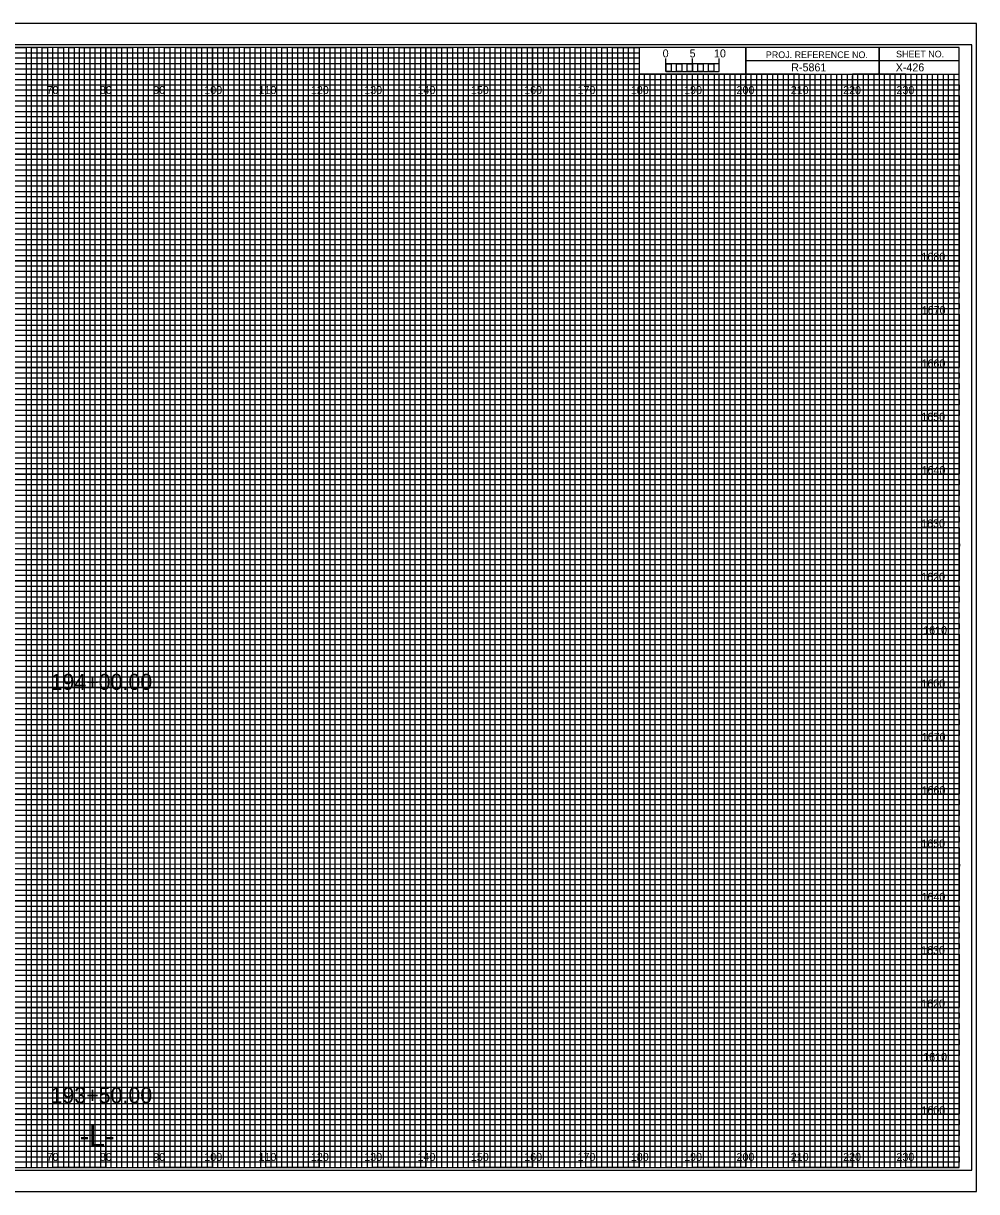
# Model space of a CAD drawing. Extents: x -13 to 323, y -5 to 6154.
# Drawn here: x 144.5 to 323.3, y 4835.5 to 5054.5 of the extents above; entities that cross this region are included whole.
import ezdxf

# ---------------------------------------------------------------- set-up
doc = ezdxf.new("R2010")
doc.units = 0
for name, color, linetype in [('Exist CMT Ground Line', 7, 'Continuous'), ('Prop Horizontal Alignment', 7, 'Continuous'), ('Prop Retaining Wall', 7, 'Continuous'), ('Prop XS Alignment Label', 7, 'Continuous'), ('Prop XS Bar Scale Labels', 7, 'Continuous'), ('Prop XS DDE', 7, 'Continuous'), ('Prop XS DDE Elevations', 7, 'Continuous'), ('Prop XS DDE Slope Text', 7, 'Continuous'), ('Prop XS Earthwork Shape', 7, 'Continuous'), ('Prop XS Elevation Labels', 7, 'Continuous'), ('Prop XS Project Number', 7, 'Continuous'), ('Prop XS Sheet Number', 7, 'Continuous'), ('Prop XS Station Labels', 7, 'Continuous'), ('Raster_Level_0', 7, 'Continuous'), ('Scratch_Level_3', 7, 'Continuous'), ('Sheet Cutting Line CELL', 7, 'Continuous')]:
    doc.layers.add(name, color=color, linetype=linetype)

msp = doc.modelspace()

# ---------------------------------------------------------------- linework, layer by layer
at = {"layer": 'Exist CMT Ground Line'}
for p, q in [((265, 5045.49), (265, 5047.9)), ((265, 5046.9), (265, 5047.9)), ((270, 5045.49), (270, 5047.9)), ((275, 5045.49), (275, 5047.9)), ((275, 5046.9), (275, 5047.9))]:
    msp.add_line(p, q, dxfattribs=at)
for points in [[(275, 5046.9), (265, 5046.9), (265, 5045.49), (275, 5045.49)], [(265, 5046.9), (266, 5046.9), (266, 5045.49), (265, 5045.49)], [(267, 5046.9), (268, 5046.9), (268, 5045.49), (267, 5045.49)], [(269, 5046.9), (270, 5046.9), (270, 5045.49), (269, 5045.49)], [(271, 5046.9), (272, 5046.9), (272, 5045.49), (271, 5045.49)], [(273, 5046.9), (274, 5046.9), (274, 5045.49), (273, 5045.49)]]:
    msp.add_lwpolyline(points, close=True, dxfattribs=at)
at = {"layer": 'Prop Retaining Wall'}
for p, q in [((0, 5049), (260, 5049)), ((260, 5047.98), (0, 5047.98)), ((260, 5049), (260, 5047.98)), ((0, 5047), (260, 5047)), ((260, 5045.89), (0, 5045.89)), ((260, 5047), (260, 5045.89)), ((0, 5044), (320, 5044))]:
    msp.add_line(p, q, dxfattribs=at)
for points in [[(0, 5043), (270, 5043), (320, 5043), (320, 5042), (0, 5042)], [(0, 5041), (320, 5041), (320, 5039), (0, 5039)], [(0, 5038), (320, 5038), (320, 5037), (0, 5036.98)], [(0, 5036), (320, 5036), (320, 5034), (0, 5034)], [(0, 5033), (320, 5033), (320, 5032), (0, 5032)], [(0, 5031), (320, 5031), (320, 5029), (0, 5029)], [(0, 5028), (320, 5028), (320, 5027), (0, 5027)], [(0, 5026), (320, 5026), (320, 5024), (0, 5024)], [(0, 5023), (320, 5023), (320, 5022), (0, 5022)], [(0, 5021), (320, 5021), (320, 5019), (0, 5019)], [(0, 5018), (320, 5018), (320, 5017), (0, 5017)], [(0, 5016), (320, 5016), (320, 5013.95), (320, 5013), (320, 5012), (0, 5012)], [(0, 5014), (320, 5014), (320, 5013), (0, 5013)], [(0, 5011), (320, 5011), (320, 5009), (0, 5009.03)], [(0, 5009.03), (320, 5009), (320, 5008), (0, 5008)], [(0, 5007), (320, 5007), (320, 5006), (0, 5006)], [(0, 5004), (320, 5004), (320, 5003), (0, 5003)], [(0, 5002), (320, 5002), (320, 5001), (0, 5001)], [(-0.07, 4998.89), (320, 4998.89), (320, 4997.88), (-0.07, 4997.88)], [(0, 4997), (320, 4997), (320, 4996), (0, 4996)], [(0, 4994), (320, 4994), (320, 4993), (0, 4993)], [(0, 4992), (320, 4992), (320, 4991), (0, 4991)], [(0, 4989), (320, 4989), (320, 4988), (0, 4988)], [(0, 4987), (320, 4987), (320, 4986), (0, 4986)], [(0, 4984), (320, 4984), (320, 4983), (0, 4983)], [(0, 4982), (320, 4982), (320, 4981), (0, 4981)], [(0, 4979), (320, 4979), (319.99, 4977.98), (0, 4978)], [(0, 4977), (320, 4977), (320, 4976), (0, 4976)], [(0, 4974), (320, 4974), (320, 4973), (0, 4973)], [(0, 4972), (320, 4972), (320, 4971), (0, 4971)], [(0, 4969), (320, 4969), (320, 4968), (0, 4968)], [(0, 4967), (320, 4967), (320, 4966), (0, 4966)], [(0, 4964), (320, 4964), (320, 4963), (0, 4963)], [(0, 4962), (320, 4962), (320, 4961), (0, 4961)], [(0, 4959), (320, 4959), (320, 4958), (0, 4958)], [(0, 4956.99), (320.07, 4956.91), (320, 4956), (0, 4956)], [(0, 4954), (320, 4954), (320, 4953), (0, 4953)], [(0, 4952), (320, 4952), (320, 4951), (0, 4951)], [(0, 4949), (320, 4949), (320, 4948), (0, 4948)], [(0, 4947), (320, 4947), (320, 4946), (0, 4946)], [(0, 4944), (320, 4944), (320, 4943), (0, 4943)], [(0, 4942), (320, 4942), (320, 4941), (0, 4941)], [(0, 4939), (320, 4939), (320, 4938), (0, 4938)], [(0, 4937), (320, 4937), (320, 4936), (0, 4936)], [(0, 4934), (320, 4934), (320, 4933), (0, 4933)], [(0, 4932), (320, 4932), (320, 4931), (0, 4931)], [(0, 4929), (320, 4929), (320, 4928), (0, 4928)], [(0, 4927), (320, 4927), (320, 4926), (0, 4926)], [(0, 4924), (320, 4924), (320, 4923), (0, 4923)], [(0, 4922), (320, 4922), (320, 4921), (0, 4921)], [(0, 4919), (320, 4919), (319.99, 4917.98), (0, 4918)], [(0, 4917), (320, 4917), (320, 4916), (0, 4916)], [(0, 4914), (320, 4914), (320, 4913), (0, 4913)], [(0, 4912), (320, 4912), (320, 4911), (0, 4911)], [(0, 4909), (320, 4909), (320, 4908), (0, 4908)], [(0, 4907), (320, 4907), (320, 4906), (0, 4906)], [(0, 4904), (320, 4904), (320, 4903), (0, 4903)], [(0, 4902), (320, 4902), (320, 4901), (0, 4901)], [(0, 4899), (320, 4899), (320, 4898), (0, 4898)], [(0, 4896.99), (320.07, 4896.91), (320, 4896), (0, 4896)], [(0, 4894), (320, 4894), (320, 4893), (0, 4893)], [(0, 4892), (320, 4892), (320, 4891), (0, 4891)], [(0, 4889), (320, 4889), (320, 4888), (0, 4888)], [(0, 4887), (320, 4887), (320, 4886), (0, 4886)], [(0, 4884), (320, 4884), (320, 4883), (0, 4883)], [(0, 4882), (320, 4882), (320, 4881), (0, 4881)], [(0, 4879), (320, 4879), (320, 4878), (0, 4878)], [(0, 4877), (320, 4877), (320, 4876), (0, 4876)], [(0, 4874), (320, 4874), (320, 4873), (0, 4873)], [(0, 4872), (320, 4872), (320, 4871), (0, 4871)], [(0, 4869), (320, 4869), (320, 4868), (0, 4868)], [(0, 4867), (320, 4867), (320, 4866), (0, 4866)], [(0, 4864), (320, 4864), (320, 4863), (0, 4863)], [(0, 4862), (320, 4862), (320, 4861), (0, 4861)], [(0, 4859), (320, 4859), (320, 4858), (0, 4858)], [(0, 4857), (320, 4857), (320, 4856), (0, 4856)], [(0, 4854), (320, 4854), (320, 4853), (0, 4853)], [(0, 4852), (320, 4852), (320, 4851), (0, 4851)], [(0, 4849), (320, 4849), (320, 4848), (0, 4848)], [(0, 4847), (320, 4847), (320, 4846), (0, 4846)], [(0, 4844), (320, 4844), (320, 4843), (0, 4843)], [(0, 4842), (320, 4842), (320, 4841), (0, 4841)]]:
    msp.add_lwpolyline(points, dxfattribs=at)
at = {"layer": 'Prop XS Alignment Label'}
for p, q in [((305, 5050), (305, 5045)), ((305, 5045), (305, 5050)), ((280, 5047.5), (280, 5045)), ((320, 5047.49), (280, 5047.49)), ((280, 5045), (320, 5045))]:
    msp.add_line(p, q, dxfattribs=at)
for points in [[(320, 5050), (0, 5050), (0, 4840), (320, 4840)], [(280, 5050), (260, 5050), (260, 5045.03), (280, 5045.03)], [(320, 5050), (280, 5050), (280, 5045), (320, 5045)]]:
    msp.add_lwpolyline(points, close=True, dxfattribs=at)
at = {"layer": 'Prop XS DDE'}
msp.add_lwpolyline([(-13.4, 4835.5), (323.3, 4835.5), (323.3, 5054.5), (-13.4, 5054.5)], close=True, dxfattribs=at)
at = {"layer": 'Prop XS DDE Elevations'}
for p, q in [((150, 4840), (150, 5050)), ((160, 4840), (160, 5050)), ((170, 4840), (170, 5050)), ((180, 4840), (180, 5050)), ((190, 4840), (190, 5050)), ((200, 4840), (200, 5050)), ((210, 4840), (210, 5050)), ((220, 4840), (220, 5050)), ((230, 4840), (230, 5050)), ((240, 4840), (240, 5050)), ((250, 4840), (250, 5050)), ((260, 4840), (260, 5044.69)), ((270, 4840), (270, 5044.69)), ((280, 4840), (280, 5044.69)), ((290, 4840), (290, 5044.69)), ((300, 4840), (300, 5044.69)), ((310, 4840), (310, 5044.69)), ((0, 5040), (320, 5040)), ((0, 5030), (320, 5030)), ((0, 5020), (320, 5020)), ((0, 5010), (320, 5010)), ((0, 5000), (320, 5000)), ((0, 4990), (320, 4990)), ((0, 4980), (320, 4980)), ((0, 4970), (320, 4970)), ((0, 4960), (320, 4960)), ((0, 4950), (320, 4950)), ((0, 4940), (320, 4940)), ((0, 4930), (320, 4930)), ((0, 4920), (320, 4920)), ((0, 4910), (320, 4910)), ((0, 4900), (320, 4900)), ((0, 4890), (320, 4890)), ((0, 4880), (320, 4880)), ((0, 4870), (320, 4870)), ((0, 4860), (320, 4860)), ((0, 4850), (320, 4850))]:
    msp.add_line(p, q, dxfattribs=at)
at = {"layer": 'Prop XS DDE Slope Text'}
msp.add_lwpolyline([(-10.8, 4839.5), (322.4, 4839.5), (322.4, 5050.5), (-10.8, 5050.5)], close=True, dxfattribs=at)
at = {"layer": 'Prop XS Earthwork Shape'}
for p, q in [((150, 5050), (140, 5050)), ((150, 4840), (150, 5050)), ((170, 5050), (160, 5050)), ((160, 5050), (160, 4840)), ((170, 4840), (170, 5050)), ((190, 5050), (180, 5050)), ((180, 5050), (180, 4840)), ((190, 4840), (190, 5050)), ((210, 5050), (200, 5050)), ((200, 5050), (200, 4840)), ((210, 4840), (210, 5050)), ((230, 5050), (220, 5050)), ((220, 5050), (220, 4840)), ((230, 4840), (230, 5050)), ((250, 5050), (240, 5050)), ((240, 5050), (240, 4840)), ((250, 4840), (250, 5050)), ((260, 5050), (260, 4840)), ((270, 4840), (270, 5045)), ((290, 5045), (280, 5045)), ((280, 5045), (280, 4840)), ((290, 4840), (290, 5045)), ((310, 5045), (300, 5045)), ((300, 5045), (300, 4840)), ((310, 4840), (310, 5045)), ((160, 4840), (150, 4840)), ((180, 4840), (170, 4840)), ((200, 4840), (190, 4840)), ((220, 4840), (210, 4840)), ((240, 4840), (230, 4840)), ((260, 4840), (250, 4840)), ((280, 4840), (270, 4840)), ((300, 4840), (290, 4840)), ((320, 4840), (310, 4840)), ((320, 4840), (320, 4840))]:
    msp.add_line(p, q, dxfattribs=at)
for points in [[(0, 5040), (320, 5040), (320, 5030), (0, 5030)], [(0, 5020), (320, 5020), (320, 5010), (0, 5010)], [(0, 5000), (320, 5000), (320, 4990), (0, 4990)], [(0, 4980), (320, 4980), (320, 4970), (0, 4970)], [(0, 4960), (320, 4960), (320, 4950), (0, 4950)], [(0, 4940), (320, 4940), (320, 4930), (0, 4930)], [(0, 4920), (320, 4920), (320, 4910), (0, 4910)], [(0, 4900), (320, 4900), (320, 4890), (0, 4890)], [(0, 4880), (320, 4880), (320, 4870), (0, 4870)], [(0, 4860), (320, 4860), (320, 4850), (0, 4850)]]:
    msp.add_lwpolyline(points, dxfattribs=at)
at = {"layer": 'Prop XS Elevation Labels'}
for p, q in [((267, 5045), (266.01, 5045)), ((266.01, 5045), (266.01, 4840)), ((267, 4840), (267, 5045)), ((269, 5045), (268, 5045)), ((268, 5045), (268, 4840)), ((269, 4840), (269, 5045)), ((266.01, 4840), (265, 4840)), ((268, 4840), (267, 4840))]:
    msp.add_line(p, q, dxfattribs=at)
for points in [[(145, 4840), (146, 4840), (146, 5050), (147, 5050), (147, 4840)], [(147, 4840), (148, 4840), (148, 5050), (149, 5050), (149, 4840)], [(150, 4840), (151, 4840), (151, 5050), (152, 5050), (152, 4840)], [(152, 4840), (153, 4840), (153, 5050), (154, 5050), (154, 4840)], [(155, 4840), (156, 4840), (156, 5050), (157, 5050), (157, 4840)], [(157, 4840), (158, 4840), (158, 5050), (159, 5050), (159, 4840)], [(160, 4840), (161, 4840), (161, 5050), (162, 5050), (162, 4840)], [(162, 4840), (163, 4840), (163, 5050), (164, 5050), (164, 4840)], [(165, 4840), (166, 4840), (166, 5050), (167, 5050), (167, 4840)], [(167, 4840), (168, 4840), (168, 5050), (169, 5050), (169, 4840)], [(170, 4840), (171, 4840), (171, 5050), (172, 5050), (172, 4840)], [(172, 4840), (173, 4840), (173, 5050), (174, 5050), (174, 4840)], [(175, 4840), (176, 4840), (176, 5050), (177, 5050), (177, 4840)], [(177, 4840), (178, 4840), (178, 5050), (179, 5050), (179, 4840)], [(180, 4840), (181, 4840), (181, 5050), (182, 5050), (182, 4840)], [(182, 4840), (183, 4840), (183, 5050), (184, 5050), (184, 4840)], [(185, 4840), (186, 4840), (186, 5050), (187, 5050), (187, 4840)], [(187, 4840), (188, 4840), (188, 5050), (189, 5050), (189, 4840)], [(190, 4840), (191, 4840), (191, 5050), (192, 5050), (192, 4840)], [(192, 4840), (193, 4840), (193, 5050), (194, 5050), (194, 4840)], [(195, 4840), (196, 4840), (196, 5050), (197, 5050), (197, 4840)], [(197, 4840), (198, 4840), (198, 5050), (199, 5050), (199, 4840)], [(200, 4840), (201, 4840), (201, 5050), (202, 5050), (202, 4840)], [(202, 4840), (203, 4840), (203, 5050), (204, 5050), (204, 4840)], [(205, 4840), (206, 4840), (206, 5050), (207, 5050), (207, 4840)], [(207, 4840), (208, 4840), (208, 5050), (209, 5050), (209, 4840)], [(210, 4840), (211, 4840), (211, 5050), (212, 5050), (212, 4840)], [(212, 4840), (213, 4840), (213, 5050), (214, 5050), (214, 4840)], [(215, 4840), (216, 4840), (216, 5050), (217, 5050), (217, 4840)], [(217, 4840), (218, 4840), (218, 5050), (219, 5050), (219, 4840)], [(220, 4840), (221, 4840), (221, 5050), (222, 5050), (222, 4840)], [(222, 4840), (223, 4840), (223, 5050), (224, 5050), (224, 4840)], [(225, 4840), (226, 4840), (226, 5050), (227, 5050), (227, 4840)], [(227, 4840), (228, 4840), (228, 5050), (229, 5050), (229, 4840)], [(230, 4840), (231, 4840), (231, 5050), (232, 5050), (232, 4840)], [(232, 4840), (233, 4840), (233, 5050), (234, 5050), (234, 4840)], [(235, 4840), (236, 4840), (236, 5050), (237, 5050), (237, 4840)], [(237, 4840), (238, 4840), (238, 5050), (239, 5050), (239, 4840)], [(240, 4840), (241, 4840), (241, 5050), (242, 5050), (242, 4840)], [(242, 4840), (243, 4840), (243, 5050), (244, 5050), (244, 4840)], [(245, 4840), (246, 4840), (246, 5050), (247, 5050), (247, 4840)], [(247, 4840), (248, 4840), (248, 5050), (249, 5050), (249, 4840)], [(250, 4840), (251, 4840), (251, 5050), (252, 5050), (252, 4840)], [(252, 4840), (253, 4840), (253, 5050), (254, 5050), (254, 4840)], [(255, 4840), (256, 4840), (256, 5050), (257, 5050), (257, 4840)], [(257, 4840), (258, 4840), (258, 5050), (259, 5050), (259, 4840)], [(260, 4840), (261, 4840), (261, 5045), (262.02, 5045), (262.02, 4840)], [(262, 4840), (263, 4840), (263, 5045), (263.99, 5045), (263.99, 4840)], [(270, 4840), (270.98, 4840), (270.98, 5045), (272, 5045), (272, 4840)], [(272, 4840), (273, 4840), (273, 5045), (274.05, 5045), (274.05, 4840)], [(275, 4840), (276, 4840), (276, 5045), (277, 5045), (277, 4840)], [(277, 4840), (278, 4840), (278, 5045), (279, 5045), (279, 4840)], [(280, 4840), (281, 4840), (281, 5045), (282, 5045), (282, 4840)], [(282, 4840), (283, 4840), (283, 5045), (284, 5045), (284, 4840)], [(285, 4840), (286, 4840), (286, 5045), (287, 5045), (287, 4840)], [(287, 4840), (288, 4840), (288, 5045), (289, 5045), (289, 4840)], [(290, 4840), (291, 4840), (291, 5045), (292, 5045), (292, 4840)], [(292, 4840), (293, 4840), (293, 5045), (294, 5045), (294, 4840)], [(295, 4840), (296, 4840), (296, 5045), (297, 5045), (297, 4840)], [(297, 4840), (298, 4840), (298, 5045), (299, 5045), (299, 4840)], [(300, 4840), (301, 4840), (301, 5045), (302, 5045), (302, 4840)], [(302, 4840), (303, 4840), (303, 5045), (304, 5045), (304, 4840)], [(305, 4840), (306, 4840), (306, 5045), (307, 5045), (307, 4840)], [(307, 4840), (308, 4840), (308, 5045), (309, 5045), (309, 4840)], [(310, 4840), (311, 4840), (311, 5045), (312, 5045), (312, 4840)], [(312, 4840), (313, 4840), (313, 5045), (314, 5045), (314, 4840)], [(315, 4840), (316, 4840), (316, 5045), (317, 5045), (317, 4840)], [(317, 4840), (318, 4840), (318, 5045), (319, 5045), (319, 4840)]]:
    msp.add_lwpolyline(points, dxfattribs=at)
at = {"layer": 'Prop XS Station Labels'}
for points in [[(135, 5050), (145, 5050), (145, 4840), (155, 4840), (155, 5050), (165, 5050), (165, 4840), (175, 4840), (175, 5050), (185, 5050), (185, 4840), (195, 4840), (195, 5050), (205, 5050), (205, 4840), (215, 4840), (215, 5050), (225, 5050), (225, 4840), (235, 4840), (235, 5050), (245, 5050), (245, 4840), (255, 4840), (255, 5050), (259.93, 5050), (260, 5050), (260, 5045), (264.99, 5045), (264.99, 4840), (275, 4840), (275, 5045), (285, 5045), (285, 4840), (295, 4840), (295, 5045), (305, 5045), (305, 4840), (315, 4840), (315, 5045)], [(0, 5045), (275, 5045)], [(0, 5025), (320, 5025), (320, 5035), (0, 5035)], [(0, 5005), (320, 5005), (320, 5015), (0, 5015)], [(0, 4985), (320, 4985), (320, 4995), (0, 4995)], [(0, 4965), (320, 4965), (320, 4975), (0, 4975)], [(0, 4945), (320, 4945), (320, 4955), (0, 4955)], [(0, 4925), (320, 4925), (320, 4935), (0, 4935)], [(0, 4905), (320, 4905), (320, 4915), (0, 4915)], [(0, 4885), (320, 4885), (320, 4895), (0, 4895)], [(0, 4865), (320, 4865), (320, 4875), (0, 4875)], [(0, 4845), (320, 4845), (320, 4855), (0, 4855)]]:
    msp.add_lwpolyline(points, dxfattribs=at)
at = {"layer": 'Sheet Cutting Line CELL'}
for p, q in [((323.3, 5054.5), (-13.4, 5054.5)), ((-13.4, 4835.5), (323.3, 4835.5))]:
    msp.add_line(p, q, dxfattribs=at)

# ---------------------------------------------------------------- texts
at = {"layer": 'Exist CMT Ground Line'}
msp.add_text('0', height=1.5, dxfattribs=at).set_placement((264.41, 5048.12))
at = {"layer": 'Prop Horizontal Alignment'}
for s, p in [('194+00.00', (149.59, 4929.56)), ('193+50.00', (149.59, 4852.08))]:
    msp.add_text(s, height=3, dxfattribs=at).set_placement(p)
at = {"layer": 'Prop XS Alignment Label'}
for s, height, p in [('PROJ. REFERENCE NO.', 1.25, (283.77, 5047.99)), ('SHEET NO.', 1.25, (308.19, 5048.12)), ('-L-', 4, (155.06, 4844))]:
    msp.add_text(s, height=height, dxfattribs=at).set_placement(p)
at = {"layer": 'Prop XS Bar Scale Labels'}
for s, p in [('5', (269.47, 5048.12)), ('10', (274.04, 5048.12))]:
    msp.add_text(s, height=1.5, dxfattribs=at).set_placement(p)
at = {"layer": 'Prop XS Project Number'}
msp.add_text('R-5861', height=1.5, dxfattribs=at).set_placement((288.53, 5045.5))
at = {"layer": 'Prop XS Sheet Number'}
msp.add_text('X-426', height=1.5, dxfattribs=at).set_placement((308.12, 5045.5))
at = {"layer": 'Raster_Level_0'}
for s, p in [('70', (148.86, 5041.25)), ('80', (158.86, 5041.25)), ('90', (168.86, 5041.25)), ('100', (178.44, 5041.25)), ('110', (188.62, 5041.25)), ('120', (198.44, 5041.25)), ('130', (208.44, 5041.25)), ('140', (218.44, 5041.25)), ('150', (228.44, 5041.25)), ('160', (238.44, 5041.25)), ('170', (248.44, 5041.25)), ('180', (258.44, 5041.25)), ('190', (268.44, 5041.25)), ('200', (278.26, 5041.25)), ('210', (288.44, 5041.25)), ('220', (298.26, 5041.25)), ('230', (308.26, 5041.25)), ('70', (148.86, 4841.25)), ('80', (158.86, 4841.25)), ('90', (168.86, 4841.25)), ('100', (178.44, 4841.25)), ('110', (188.62, 4841.25)), ('120', (198.44, 4841.25)), ('130', (208.44, 4841.25)), ('140', (218.44, 4841.25)), ('150', (228.44, 4841.25)), ('160', (238.44, 4841.25)), ('170', (248.44, 4841.25)), ('180', (258.44, 4841.25)), ('190', (268.44, 4841.25)), ('200', (278.26, 4841.25)), ('210', (288.44, 4841.25)), ('220', (298.26, 4841.25)), ('230', (308.26, 4841.25))]:
    msp.add_text(s, height=1.5, dxfattribs=at).set_placement(p)
at = {"layer": 'Scratch_Level_3'}
for s, p in [('1680', (312.95, 5010)), ('1670', (313, 5000)), ('1660', (312.97, 4990)), ('1650', (312.92, 4980)), ('1640', (312.97, 4970)), ('1630', (312.89, 4960)), ('1620', (312.9, 4950)), ('1610', (313.28, 4940)), ('1600', (312.95, 4930)), ('1670', (313, 4920)), ('1660', (312.97, 4910)), ('1650', (312.92, 4900)), ('1640', (312.97, 4890)), ('1630', (312.89, 4880)), ('1620', (312.9, 4870)), ('1610', (313.28, 4860)), ('1600', (312.95, 4850))]:
    msp.add_text(s, height=1.5, dxfattribs=at).set_placement(p)

doc.saveas('drawing.dxf')
